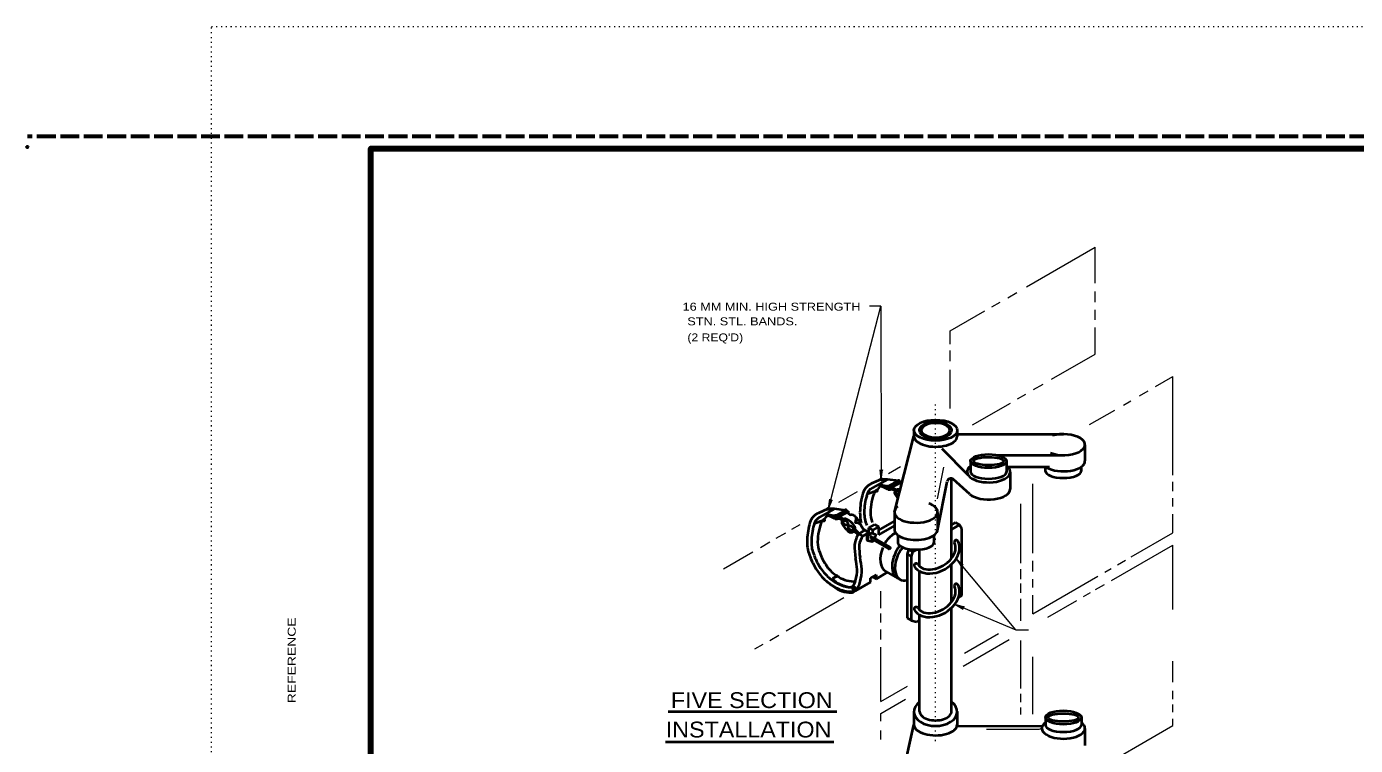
# Model space of a CAD drawing. Extents: x 312583 to 312854, y 144419 to 144597.
# Drawn here: x 312583.5 to 312711, y 144527.8 to 144596.8 of the extents above; entities that cross this region are included whole.
import ezdxf
from ezdxf.enums import TextEntityAlignment as Align

# ---------------------------------------------------------------- set-up
doc = ezdxf.new("R2010")
doc.units = 0
doc.header["$LTSCALE"] = 0.3
doc.header["$PDMODE"] = 32
doc.header["$PDSIZE"] = 0.15
doc.linetypes.add('DOTTED', pattern=[1.5, 0.3, -1.2])
doc.linetypes.add('LONG_DASHED', pattern=[7.5, 6, -1.5])
for name, color, linetype, lineweight in [('1', 7, 'Continuous', 40), ('2', 7, 'Continuous', 40), ('62', 7, 'DOTTED', 13), ('63', 7, 'LONG_DASHED', 60)]:
    doc.layers.add(name, color=color, linetype=linetype, lineweight=lineweight)

msp = doc.modelspace()

# ---------------------------------------------------------------- linework, layer by layer
at = {"layer": '1', "lineweight": 13}
for p, q in [((312679.4271, 144571.7997), (312686.0281, 144575.6177)), ((312686.0281, 144572.16), (312686.0281, 144575.6177)), ((312676.0997, 144569.883), (312676.8971, 144570.343)), ((312677.6331, 144570.7723), (312678.5147, 144571.2783)), ((312686.0281, 144570.3277), (312686.0281, 144571.355)), ((312672.1054, 144567.5753), (312675.4481, 144569.5073)), ((312686.0281, 144568.641), (312686.0281, 144569.5917)), ((312686.0281, 144565.3597), (312686.0281, 144567.905)), ((312672.1054, 144566.3257), (312672.1054, 144567.5753)), ((312672.1054, 144564.6773), (312672.1054, 144565.7047)), ((312681.8421, 144562.9447), (312686.0281, 144565.3597)), ((312672.1054, 144560.131), (312672.1054, 144563.834)), ((312691.8164, 144562.2393), (312693.4647, 144563.1977)), ((312693.4647, 144553.7447), (312693.4647, 144563.1977)), ((312678.5761, 144561.0587), (312679.3734, 144561.5187)), ((312680.1094, 144561.948), (312681.0217, 144562.477)), ((312690.2754, 144561.3577), (312691.0957, 144561.8253)), ((312674.2521, 144558.5593), (312677.8861, 144560.66)), ((312685.4914, 144558.59), (312687.9141, 144559.993)), ((312688.7344, 144560.4607), (312689.4551, 144560.8747)), ((312666.1714, 144553.898), (312667.3291, 144554.565)), ((312670.8941, 144551.4753), (312671.4844, 144554.496)), ((312680.0327, 144546.262), (312680.0327, 144552.9013)), ((312693.4647, 144552.2113), (312693.4647, 144553.0853)), ((312661.4257, 144551.161), (312663.2121, 144552.1883)), ((312693.4647, 144550.7393), (312693.4647, 144551.5443)), ((312678.8827, 144545.3113), (312678.8827, 144551)), ((312693.4647, 144548.194), (312693.4647, 144550.0033)), ((312656.9024, 144548.5467), (312657.6997, 144549.0067)), ((312653.9047, 144546.814), (312654.7864, 144547.3277)), ((312655.3997, 144547.6803), (312656.3274, 144548.2093)), ((312689.4934, 144545.894), (312693.4647, 144548.194)), ((312650.3321, 144544.7517), (312653.1687, 144546.3923)), ((312687.5767, 144543.64), (312693.4647, 144547.0363)), ((312693.4647, 144540.8417), (312693.4647, 144547.0363)), ((312678.8827, 144543.7703), (312678.8827, 144544.7287)), ((312680.0327, 144544.5063), (312680.0327, 144545.5337)), ((312686.9557, 144544.4297), (312687.5537, 144544.7747)), ((312688.1824, 144545.1427), (312688.9261, 144545.572)), ((312680.0327, 144540.4353), (312686.2734, 144544.0387)), ((312680.0327, 144542.9653), (312680.0327, 144543.7703)), ((312665.4507, 144540.9873), (312665.4507, 144542.6127)), ((312678.8827, 144542.4517), (312678.8827, 144543.3333)), ((312680.0327, 144540.4353), (312680.0327, 144542.2293)), ((312684.8934, 144542.0913), (312685.5604, 144542.4747)), ((312686.0587, 144542.766), (312686.9251, 144543.2567)), ((312656.3504, 144538.7947), (312661.8857, 144541.9917)), ((312678.8827, 144539.7683), (312678.8827, 144541.8613)), ((312681.4894, 144540.121), (312684.2647, 144541.7233)), ((312665.4507, 144539.592), (312665.4507, 144540.4737)), ((312654.7864, 144537.89), (312655.6681, 144538.396)), ((312665.4507, 144537.9743), (312665.4507, 144538.9327)), ((312673.4931, 144536.6557), (312676.7514, 144538.5417)), ((312653.3604, 144537.062), (312654.1577, 144537.522)), ((312665.4507, 144532.0097), (312665.4507, 144537.246)), ((312673.3397, 144535.4213), (312677.7634, 144537.9743)), ((312678.8827, 144533.2823), (312678.8827, 144537.8747)), ((312680.0327, 144530.8137), (312680.0327, 144536.3107)), ((312693.4647, 144533.865), (312693.4647, 144535.9043)), ((312665.4507, 144532.0097), (312668.0114, 144533.497)), ((312665.4507, 144530.8597), (312667.8197, 144532.232)), ((312678.8827, 144531.9637), (312678.8827, 144532.7687)), ((312693.4647, 144532.255), (312693.4647, 144533.06)), ((312665.4507, 144530.1237), (312665.4507, 144530.8597)), ((312678.8827, 144530.76), (312678.8827, 144531.45)), ((312693.4647, 144531.0053), (312693.4647, 144531.7413)), ((312675.5784, 144529.3647), (312680.5617, 144529.357)), ((312685.0774, 144524.8643), (312693.4647, 144529.7097)), ((312693.4647, 144529.7097), (312693.4647, 144530.346)), ((312665.4507, 144528.368), (312665.4507, 144529.2497))]:
    msp.add_line(p, q, dxfattribs=at)
at = {"layer": '1', "linetype": 'DOTTED', "lineweight": 13}
msp.add_line((312670.7024, 144528.23), (312670.7024, 144560.683), dxfattribs=at)
at = {"layer": '1'}
for p, q in [((312666.7541, 144550.1873), (312668.6324, 144557.4783)), ((312668.6324, 144558.0533), (312668.6324, 144557.4783)), ((312672.7801, 144558.038), (312672.7801, 144557.463)), ((312672.7801, 144557.67), (312682.9767, 144557.67)), ((312673.8381, 144553.7293), (312671.3311, 144556.2747)), ((312685.0391, 144556.658), (312685.0391, 144555.1093)), ((312674.0681, 144555.094), (312674.0681, 144554.059)), ((312676.6211, 144555.6613), (312682.9691, 144555.6613)), ((312677.5257, 144555.0863), (312677.5257, 144554.0437)), ((312681.6504, 144554.496), (312677.5257, 144554.496)), ((312677.8707, 144554.0437), (312677.8707, 144552.3953)), ((312681.2364, 144554.496), (312681.2364, 144554.1433)), ((312684.6941, 144554.5497), (312684.6941, 144554.128)), ((312665.4431, 144553.3307), (312664.5461, 144552.932)), ((312666.0871, 144553.3383), (312664.6457, 144552.5257)), ((312666.0871, 144553.3383), (312665.4431, 144553.3307)), ((312667.1527, 144553.185), (312666.1484, 144552.6407)), ((312666.1484, 144552.38), (312666.1484, 144552.6407)), ((312667.3444, 144553.0163), (312666.3784, 144552.5103)), ((312666.3784, 144552.38), (312666.3784, 144552.5103)), ((312667.1527, 144553.185), (312667.3444, 144553.0163)), ((312670.8864, 144548.4163), (312671.8064, 144553.116)), ((312672.2357, 144545.756), (312672.2357, 144553.4227)), ((312673.9991, 144551.9123), (312672.4044, 144553.3537)), ((312665.0521, 144552.242), (312664.1244, 144551.9123)), ((312660.3677, 144550.5093), (312659.4631, 144550.103)), ((312661.0041, 144550.517), (312659.5704, 144549.6967)), ((312661.0041, 144550.517), (312660.3677, 144550.5093)), ((312662.0774, 144550.3637), (312661.0731, 144549.8117)), ((312661.0731, 144549.551), (312661.0731, 144549.8117)), ((312662.2691, 144550.1873), (312661.3031, 144549.6813)), ((312662.0774, 144550.3637), (312662.2691, 144550.1873)), ((312666.7541, 144550.1873), (312666.7541, 144548.539)), ((312670.9017, 144550.172), (312670.9017, 144548.5237)), ((312659.9767, 144549.413), (312659.0491, 144549.0833)), ((312661.3031, 144549.551), (312661.3031, 144549.6813)), ((312663.3347, 144548.125), (312663.9097, 144548.4623)), ((312663.8177, 144548.516), (312664.2931, 144548.24)), ((312664.2931, 144548.677), (312664.8681, 144549.0143)), ((312664.2931, 144548.677), (312664.6764, 144548.4623)), ((312664.2931, 144548.056), (312664.2931, 144548.677)), ((312664.6764, 144548.4623), (312665.2514, 144548.792)), ((312664.6764, 144548.1557), (312664.6764, 144548.4623)), ((312664.8681, 144549.0143), (312665.2514, 144548.792)), ((312665.2514, 144548.47), (312666.7541, 144549.3363)), ((312665.2514, 144548.0253), (312666.7541, 144548.8917)), ((312665.2514, 144548.0253), (312665.2514, 144548.792)), ((312672.2357, 144548.9607), (312672.6191, 144549.183)), ((312672.2357, 144548.516), (312673.0024, 144548.9607)), ((312672.6191, 144549.183), (312673.0024, 144548.9607)), ((312673.0024, 144548.9607), (312673.2247, 144548.5773)), ((312673.2247, 144542.1833), (312673.2247, 144548.5773)), ((312663.3347, 144548.125), (312663.7181, 144547.9027)), ((312663.7181, 144547.9027), (312664.2931, 144548.24)), ((312664.4924, 144547.6497), (312666.2021, 144546.6607)), ((312664.5921, 144547.826), (312666.3094, 144546.8447)), ((312667.0914, 144547.9793), (312667.0914, 144547.2587)), ((312670.5491, 144547.964), (312670.5491, 144547.251)), ((312668.0191, 144540.0213), (312668.0191, 144546.1547)), ((312668.0191, 144546.1547), (312668.4024, 144545.9323)), ((312668.1417, 144546.5917), (312668.2184, 144546.6377)), ((312668.4024, 144545.9323), (312668.5251, 144546.3693)), ((312668.4024, 144539.799), (312668.4024, 144545.9323)), ((312668.5251, 144546.3693), (312668.9161, 144546.5993)), ((312669.1691, 144544.9817), (312669.1691, 144546.6147)), ((312672.2357, 144541.5777), (312672.2357, 144545.1963)), ((312661.3414, 144544.0923), (312660.7971, 144543.824)), ((312663.0127, 144542.6433), (312664.4464, 144543.4637)), ((312664.4464, 144543.847), (312665.0214, 144544.1767)), ((312664.4464, 144543.4637), (312664.4464, 144543.847)), ((312664.6841, 144543.985), (312665.0214, 144543.7933)), ((312665.0214, 144543.7933), (312666.1024, 144544.422)), ((312665.0214, 144543.7933), (312665.0214, 144544.1767)), ((312667.0837, 144543.8547), (312665.9491, 144544.5063)), ((312669.1691, 144540.7957), (312669.1691, 144544.514)), ((312672.9104, 144542.007), (312673.2247, 144542.1833)), ((312672.2357, 144531.0513), (312672.2357, 144541.0103)), ((312668.8701, 144539.6763), (312669.1691, 144539.845)), ((312669.1691, 144531.0513), (312669.1691, 144540.3357)), ((312668.6324, 144531.0513), (312668.6324, 144529.7863)), ((312672.7801, 144531.0513), (312672.7801, 144529.771)), ((312667.2677, 144523.8063), (312668.6324, 144529.7863)), ((312672.7801, 144529.6713), (312680.9451, 144529.6637)), ((312681.2441, 144530.4917), (312681.2441, 144529.7633)), ((312684.7017, 144530.484), (312684.7017, 144529.748)), ((312685.0391, 144529.4413), (312685.0391, 144527.8083))]:
    msp.add_line(p, q, dxfattribs=at)
at = {"layer": '1', "lineweight": 158}
msp.add_lwpolyline([(312616.5, 144423.1446), (312616.5, 144585.0846), (312849, 144585.0846)], dxfattribs=at)
at = {"layer": '1'}
for points in [[(312668.0191, 144546.1547), (312668.1417, 144546.5917), (312668.5251, 144546.3693)], [(312668.0191, 144540.0213), (312668.4024, 144539.799), (312668.8701, 144539.6763)]]:
    msp.add_lwpolyline(points, dxfattribs=at)
for centre, radius, start, end in [((312672.1798, 144553.0441), 0.3833, 54.34676, 168.95653), ((312672.6955, 144547.298), 0.1955, 41.4185, 198.58295), ((312668.8423, 144545.0731), 0.1955, 41.4185, 198.58295), ((312662.3461, 144545.1133), 2.0169, 219.82129, 245.89632), ((312672.6955, 144543.1158), 0.1955, 41.4185, 198.58295), ((312668.8423, 144540.8909), 0.1955, 41.4185, 198.58295)]:
    msp.add_arc(centre, radius, start, end, dxfattribs=at)
for centre, major_axis, ratio in [((312670.7047, 144558.0483), (2.0738, -0.0073), 0.484108), ((312670.7047, 144558.048), (1.5333, 0), 0.5475), ((312670.7047, 144558.048), (1.3417, 0), 0.542286), ((312675.7954, 144555.0898), (1.7278, -0.0061), 0.380773), ((312675.7954, 144555.0898), (1.4632, -0.0051), 0.268821), ((312682.9714, 144530.4875), (1.7278, -0.0061), 0.380773), ((312682.9714, 144530.4875), (1.4632, -0.0051), 0.268821)]:
    msp.add_ellipse(centre, major_axis=major_axis, ratio=ratio, dxfattribs=at)
for centre, major_axis, ratio, start_param, end_param in [((312670.7047, 144557.4733), (2.0738, -0.0073), 0.484108, 3.14159265, 6.28318531), ((312682.9714, 144556.6691), (2.0738, -0.0073), 0.484108, 4.0695879, 8.3811914), ((312682.9714, 144555.1136), (2.0738, -0.0073), 0.484108, 3.8185075, 6.29769365), ((312675.7954, 144554.0532), (2.0738, -0.0073), 0.484108, 2.55720954, 6.35220324), ((312675.7954, 144554.0532), (1.7278, -0.0061), 0.380773, 3.14207742, 6.28367007), ((312675.7915, 144554.0939), (2.0738, -0.0073), 0.484108, 0.02856323, 0.58722461), ((312682.966, 144554.1361), (1.7278, -0.0061), 0.380773, 3.14207742, 6.28367007), ((312675.7954, 144552.4026), (2.0738, -0.0073), 0.484108, 3.66261954, 6.28318531), ((312668.821, 144550.2215), (2.0738, -0.0073), 0.484108, 0.02825601, 0.92827925), ((312668.8248, 144550.1808), (2.0738, -0.0073), 0.484108, 2.55720954, 6.35220324), ((312668.8248, 144548.5302), (2.0738, -0.0073), 0.484108, 3.14159265, 6.28318531), ((312666.8097, 144546.359), (0.8606, 1.8526), 0.612072, 0.59924983, 1.37241803), ((312668.821, 144547.2568), (1.7278, -0.0061), 0.380773, 3.14207742, 6.28367007), ((312670.7497, 144546.2193), (2.0927, 1.2082), 0.712873, 3.14159265, 6.28318531), ((312670.7497, 144546.2193), (1.7607, 1.0166), 0.658737, 3.14159265, 6.28318531), ((312666.8097, 144546.359), (0.8606, 1.8526), 0.612072, 1.61895398, 3.1415927), ((312667.9497, 144545.7012), (0.8606, 1.8526), 0.612072, 1.13526071, 3.21281338), ((312668.2234, 144545.5425), (0.8606, 1.8526), 0.612072, 1.13028817, 3.64840316), ((312670.7497, 144542.0372), (2.0927, 1.2082), 0.712873, 3.14159265, 6.28318531), ((312670.7497, 144542.0372), (1.7607, 1.0166), 0.658737, 3.14159265, 6.28318531), ((312670.7047, 144531.0513), (2.0738, 0), 0.665434, 2.40290643, 7.0218452), ((312670.7047, 144531.0513), (1.5333, 0), 0.5475, 3.14159265, 6.28318531), ((312670.7047, 144529.7768), (2.0738, -0.0073), 0.484108, 3.14159265, 6.28318531), ((312682.9714, 144529.4509), (2.0738, -0.0073), 0.484108, 2.55749369, 6.28318531), ((312682.9714, 144529.7576), (1.7278, -0.0061), 0.380773, 3.14207742, 6.28367007), ((312682.9714, 144529.4509), (2.0738, -0.0073), 0.484108, 6.28318526, 6.87068466)]:
    msp.add_ellipse(centre, major_axis=major_axis, ratio=ratio, start_param=start_param, end_param=end_param, dxfattribs=at)
msp.add_spline([(312663.8177, 144548.516), (312663.6567, 144548.7537), (312663.5417, 144548.9607), (312663.3807, 144549.0833), (312663.1891, 144549.1677), (312662.9591, 144549.1677)], degree=3, dxfattribs=at)
for p in [(312583.526, 144585.2246), (312665.0521, 144552.242), (312665.4967, 144553.3307), (312666.1484, 144552.6407), (312667.1527, 144553.185), (312667.3444, 144553.0163), (312660.4214, 144550.5093), (312661.0731, 144549.8117), (312662.0774, 144550.3637), (312662.2691, 144550.1873), (312659.9767, 144549.413)]:
    msp.add_point(p, dxfattribs=at)
at = {"layer": '2', "lineweight": 13}
for p, q in [((312665.4431, 144569.952), (312664.3774, 144569.952)), ((312665.3817, 144554.2583), (312665.4967, 144553.9593)), ((312665.4967, 144553.3307), (312665.3817, 144554.2583)), ((312665.6117, 144554.2583), (312665.4967, 144553.9593)), ((312665.4967, 144553.3307), (312665.6117, 144554.2583)), ((312660.4214, 144550.5093), (312660.5441, 144551.4293)), ((312660.4214, 144550.5093), (312660.7664, 144551.3757)), ((312660.5441, 144551.4293), (312660.5824, 144551.115)), ((312660.7664, 144551.3757), (312660.5824, 144551.115)), ((312672.6804, 144545.733), (312673.1864, 144544.951)), ((312672.6804, 144545.733), (312673.3627, 144545.0967)), ((312673.1864, 144544.951), (312673.0867, 144545.25)), ((312673.3627, 144545.0967), (312673.0867, 144545.25)), ((312672.5501, 144541.3553), (312673.3551, 144540.8953)), ((312672.5501, 144541.3553), (312673.4471, 144541.1023)), ((312673.3551, 144540.8953), (312673.1327, 144541.1177)), ((312673.4471, 144541.1023), (312673.1327, 144541.1177)), ((312678.3997, 144538.902), (312679.6341, 144538.902))]:
    msp.add_line(p, q, dxfattribs=at)
at = {"layer": '2'}
for p, q in [((312666.1484, 144552.6407), (312665.2207, 144552.8247)), ((312666.1484, 144552.38), (312665.2207, 144552.8247)), ((312667.1527, 144553.185), (312666.0794, 144553.3383)), ((312666.1484, 144552.6407), (312666.3784, 144552.5103)), ((312666.1484, 144552.38), (312666.3784, 144552.38)), ((312661.0731, 144549.8117), (312660.1454, 144550.0033)), ((312661.0731, 144549.551), (312660.1454, 144550.0033)), ((312662.0774, 144550.3637), (312661.0041, 144550.517)), ((312661.0731, 144549.8117), (312661.3031, 144549.6813)), ((312661.0731, 144549.551), (312661.3031, 144549.551)), ((312664.2011, 144547.8797), (312664.1244, 144547.9103)), ((312664.2011, 144547.4503), (312664.1244, 144547.4887)), ((312660.7971, 144543.824), (312660.7971, 144543.6553)), ((312645.0497, 144531.0513), (312661.2333, 144531.0513)), ((312644.7737, 144528.161), (312660.9531, 144528.161))]:
    msp.add_line(p, q, dxfattribs=at)
at = {"layer": '2', "lineweight": 13}
for points in [[(312660.4214, 144550.5093), (312665.4431, 144569.952), (312665.4967, 144553.3307)], [(312672.5501, 144541.3553), (312678.3997, 144538.902), (312672.6804, 144545.733)]]:
    msp.add_lwpolyline(points, dxfattribs=at)
at = {"layer": '2'}
for points in [[(312664.1244, 144547.4887), (312664.1244, 144547.9103), (312664.5001, 144548.24)], [(312664.6917, 144547.4043), (312664.6074, 144547.3353), (312664.2011, 144547.4503), (312664.2011, 144547.8797), (312664.5767, 144548.2017)], [(312664.5001, 144548.24), (312664.9447, 144548.033), (312664.8987, 144547.7493)]]:
    msp.add_lwpolyline(points, dxfattribs=at)
msp.add_circle((312662.9223, 144542.8841), 0.1029, dxfattribs=at)
for centre, radius, start, end in [((312665.1255, 144551.5872), 1.463, 113.4944, 170.25146), ((312665.1255, 144551.5872), 1.0521, 117.27579, 170.26326), ((312666.0428, 144551.8045), 1.0807, 122.75342, 156.24987), ((312666.3709, 144551.4795), 1.0286, 56.63896, 89.41157), ((312666.3474, 144551.5168), 0.8631, 56.35231, 87.73718), ((312667.0965, 144552.0495), 0.3285, 56.49377, 213.03039), ((312665.8364, 144549.8906), 2.8278, 58.87002, 59.37458), ((312667.73, 144553.1842), 0.4186, 203.98379, 226.98319), ((312669.7377, 144550.1299), 6.2896, 164.27112, 179.6093), ((312669.7377, 144550.1299), 5.8785, 163.85628, 179.61187), ((312669.7377, 144550.1299), 5.2802, 157.21853, 179.60946), ((312669.8376, 144553.7332), 3.5457, 211.68624, 219.14675), ((312660.0494, 144548.762), 1.463, 113.4944, 170.25146), ((312660.9667, 144548.9793), 1.0807, 122.75342, 156.24987), ((312662.654, 144550.3588), 0.4186, 203.94824, 258.8033), ((312662.2517, 144548.3827), 1.598, 62.74086, 78.41262), ((312660.3338, 144547.396), 3.581, 22.64793, 42.35856), ((312662.7369, 144549.5433), 0.3583, 343.34003, 46.49264), ((312666.8084, 144550.0879), 3.3613, 178.55302, 195.74317), ((312666.8084, 144550.0879), 2.9501, 178.55988, 202.91317), ((312666.8084, 144550.0879), 2.3519, 178.0999, 201.88017), ((312664.6616, 144547.3047), 6.2896, 164.27112, 179.6093), ((312664.6616, 144547.3047), 5.8785, 163.85628, 179.61187), ((312660.0494, 144548.762), 1.0521, 117.27579, 170.26326), ((312664.6616, 144547.3047), 5.2802, 157.21853, 179.60946), ((312661.2948, 144548.6543), 1.0286, 56.63896, 89.41157), ((312661.2713, 144548.6916), 0.8631, 56.35231, 87.73718), ((312662.0204, 144549.2243), 0.3285, 56.49377, 213.03039), ((312664.7621, 144550.9078), 3.5457, 211.68938, 225.88581), ((312660.7608, 144547.0653), 2.8278, 41.7173, 59.36275), ((312662.5828, 144548.6547), 0.411, 225.35697, 45.35697), ((312662.8256, 144547.9396), 0.5434, 20.20363, 76.82698), ((312662.5585, 144549.4988), 0.525, 320.05888, 353.63969), ((312661.7323, 144547.2627), 3.3613, 178.55302, 204.0436), ((312661.7323, 144547.2627), 2.9501, 178.55302, 204.0436), ((312661.7323, 144547.2627), 2.3519, 178.55302, 204.0436), ((312662.281, 144547.1224), 1.3347, 42.74641, 65.22272), ((312665.2117, 144546.8114), 2.2917, 144.95529, 173.67348), ((312665.2117, 144546.8114), 1.8515, 143.7376, 173.66624), ((312664.504, 144548.0544), 5.8175, 200.30362, 215.79827), ((312664.504, 144548.0544), 5.2207, 199.58346, 215.79673), ((312670.4365, 144546.9125), 7.5061, 178.84408, 188.85728), ((312670.4365, 144546.9125), 7.0657, 179.16406, 188.86043), ((312664.504, 144548.0544), 6.2284, 200.30362, 215.79827), ((312663.1623, 144547.0824), 4.1602, 215.75338, 234.24661), ((312663.1623, 144547.0824), 3.5638, 215.73844, 238.06986), ((312652.8078, 144543.6589), 10.4246, 5.58543, 11.49549), ((312659.3484, 144544.7195), 3.8348, 343.40906, 359.95333), ((312652.8078, 144543.6589), 10.8653, 5.58543, 11.49549), ((312659.3484, 144544.7195), 4.273, 343.95928, 359.95812), ((312663.1831, 144547.0532), 4.5715, 215.30338, 233.79661), ((312662.9404, 144546.5057), 3.985, 231.96521, 253.10585), ((312662.9404, 144546.5057), 3.5656, 231.72375, 253.10414), ((312661.4621, 144544.0824), 0.1209, 176.75287, 242.65404), ((312662.9404, 144546.5057), 2.9591, 238.78044, 271.31191), ((312661.6967, 144543.8872), 1.3546, 323.40146, 348.79378), ((312661.6967, 144543.8872), 1.7926, 316.10835, 348.79249), ((312662.538, 144544.9433), 2.4774, 228.83035, 271.6015), ((312663.9267, 144549.3465), 6.5331, 248.40532, 256.45217), ((312662.538, 144544.9433), 2.3742, 251.44116, 268.72787), ((312662.538, 144544.9433), 1.9548, 251.44116, 268.72787), ((312662.4298, 144543.7189), 1.1493, 272.80756, 296.07535), ((312662.4322, 144543.7207), 0.7314, 274.8889, 298.77673), ((312662.4811, 144543.2406), 0.7848, 279.25201, 310.25556), ((312662.9284, 144542.9095), 0.223, 130.28049, 331.64849)]:
    msp.add_arc(centre, radius, start, end, dxfattribs=at)
at = {"layer": '2', "lineweight": 13}
msp.add_arc((312680.5614, 144529.7406), 0.3833, 269.93944, 328.16427, dxfattribs=at)
at = {"layer": '2'}
for centre, major_axis, ratio, start_param, end_param in [((312667.1443, 144551.9951), (0.1909, -0.2009), 0.623232, 1.66115454, 5.36596034), ((312664.5522, 144547.7332), (0.0422, 0.0943), 0.763111, 6.28318531, 9.16655504)]:
    msp.add_ellipse(centre, major_axis=major_axis, ratio=ratio, start_param=start_param, end_param=end_param, dxfattribs=at)
for centre, major_axis, ratio in [((312662.0682, 144549.17), (0.1909, -0.2009), 0.623232), ((312662.575, 144548.6632), (0.1909, -0.2009), 0.623232), ((312666.2634, 144546.7481), (0.0422, 0.0943), 0.763111)]:
    msp.add_ellipse(centre, major_axis=major_axis, ratio=ratio, dxfattribs=at)
at = {"layer": '62'}
for p, q in [((312601.2, 144596.7846), (312853.5, 144596.7846)), ((312601.2, 144418.5846), (312601.2, 144596.7846))]:
    msp.add_line(p, q, dxfattribs=at)
at = {"layer": '63'}
msp.add_line((312851.75, 144586.2246), (312583.526, 144586.2246), dxfattribs=at)

# ---------------------------------------------------------------- texts
at = {"layer": '1', "width": 1.3}
msp.add_text('REFERENCE                                                              ', height=0.7682, rotation=90, dxfattribs=at).set_placement((312609.2854, 144531.8549))
at = {"layer": '2'}
for s, width, p in [(' 16 MM MIN. HIGH STRENGTH', 1.2, (312646.0819, 144569.527)), ('STN. STL. BANDS.', 1.2, (312646.872, 144568.1198)), ("(2 REQ'D)", 1.15, (312646.8807, 144566.58))]:
    msp.add_text(s, height=0.76, dxfattribs=dict(at, width=width)).set_placement(p)
at = {"layer": '2', "width": 1.1}
for s, p in [('FIVE SECTION', (312653.0589, 144531.39)), ('INSTALLATION', (312652.7543, 144528.5699))]:
    msp.add_text(s, height=1.52, dxfattribs=at).set_placement(p, align=Align.CENTER)

doc.saveas('drawing.dxf')
